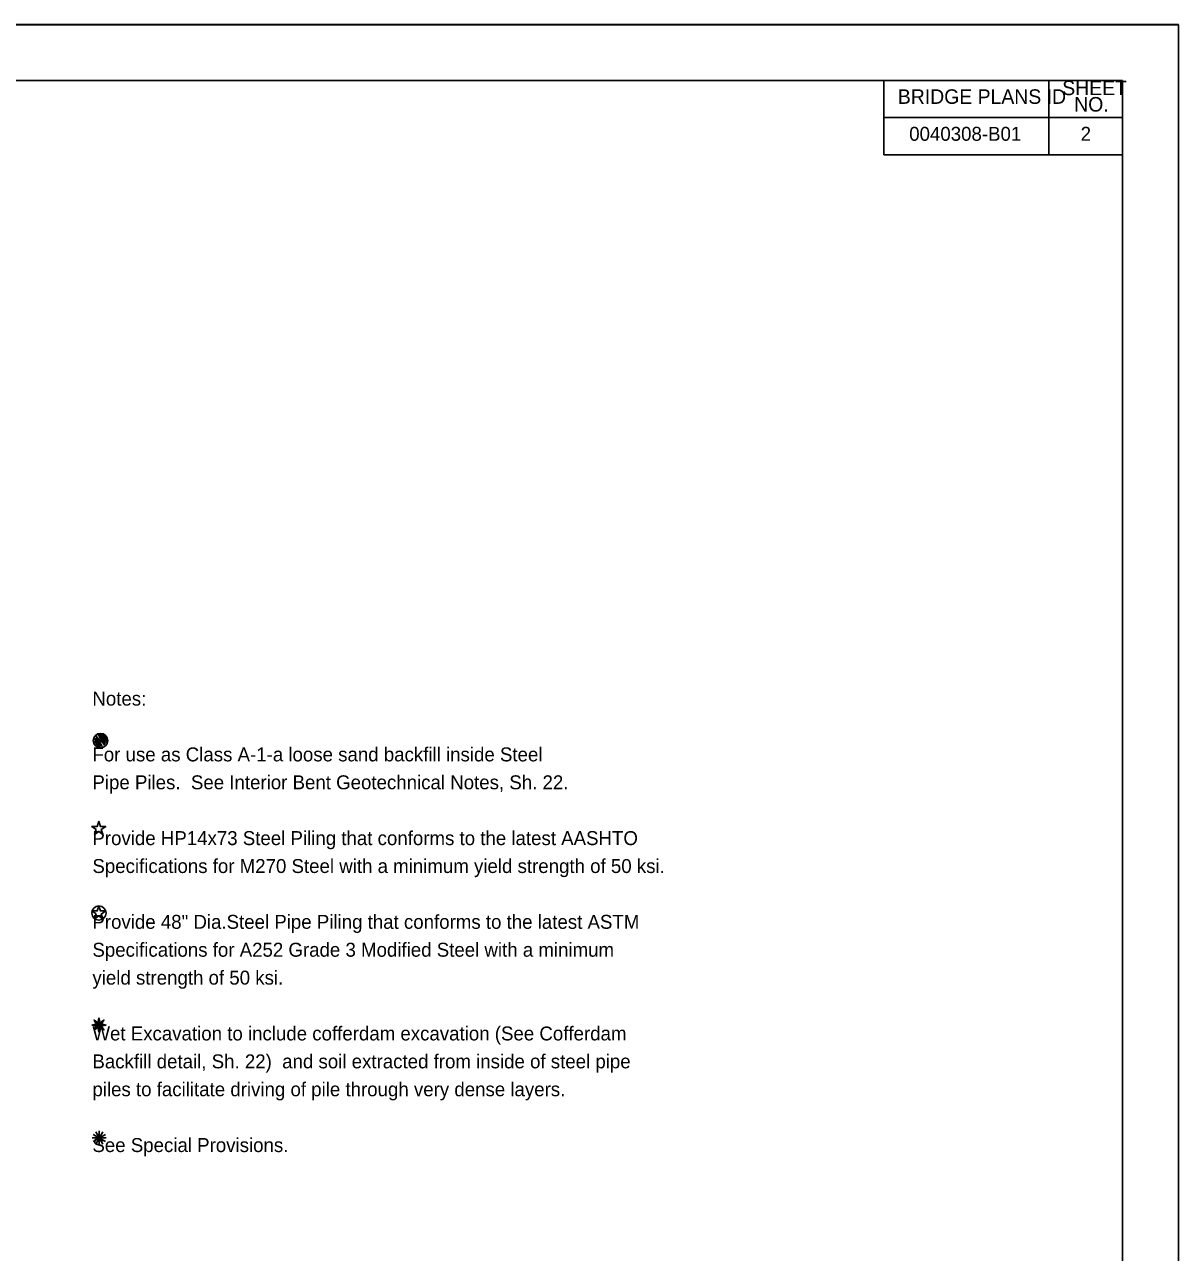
# Model space of a CAD drawing. Extents: x 1334.3 to 1370.4, y 717.9 to 739.9.
# Drawn here: x 1360 to 1370.33, y 728.87 to 739.87 of the extents above; entities that cross this region are included whole.
import ezdxf

# ---------------------------------------------------------------- set-up
doc = ezdxf.new("R2010")
doc.units = 0
for name, color, linetype in [('BR_AUTO DIMENSION', 7, 'Continuous'), ('BR_BORDER LINES', 7, 'Continuous'), ('BR_TEXT', 7, 'Continuous'), ('Default', 7, 'Continuous'), ('RD_SHT_IplotShp', 7, 'Continuous')]:
    doc.layers.add(name, color=color, linetype=linetype)

# ---------------------------------------------------------------- blocks, each defined once
blk = doc.blocks.new('BUBB')
at = {"layer": 'Default'}
for p, q in [((-2.9961, 4.5593), (0, 6.2527)), ((0, 6.2527), (-2.9961, 3.7777)), ((-2.9961, 3.7777), (0.6514, 5.9922)), ((0.6514, 5.9922), (-2.9961, 3.1264)), ((1.433, 5.4711), (-3.2566, 2.0842)), ((-3.2566, 2.0842), (1.954, 5.0803)), ((-2.9961, 3.1264), (1.433, 5.4711)), ((1.954, 5.0803), (-2.475, 1.1724)), ((-2.475, 1.1724), (2.4751, 4.0382)), ((2.4751, 4.0382), (-1.4329, 1.1724)), ((-1.4329, 1.1724), (2.6054, 3.1264)), ((2.6054, 3.1264), (-1.1723, 0.6513)), ((-1.1723, 0.6513), (2.6054, 2.475)), ((2.6054, 2.475), (0.1303, 0.6513))]:
    blk.add_line(p, q, dxfattribs=at)
blk.add_circle((-0.1667, 3.3444), 3.2509, dxfattribs=at)

msp = doc.modelspace()

# ---------------------------------------------------------------- linework, layer by layer
at = {"layer": 'BR_AUTO DIMENSION'}
for points in [[(1360.632, 730.91), (1360.601, 730.903), (1360.632, 730.896)], [(1360.646, 730.93), (1360.619, 730.947), (1360.636, 730.92)], [(1360.632, 730.91), (1360.663, 730.903), (1360.632, 730.896)], [(1360.646, 730.93), (1360.663, 730.903), (1360.636, 730.92)], [(1360.636, 730.886), (1360.663, 730.903), (1360.646, 730.876)], [(1360.67, 730.934), (1360.663, 730.965), (1360.656, 730.934)], [(1360.67, 730.934), (1360.663, 730.903), (1360.656, 730.934)], [(1360.656, 730.872), (1360.663, 730.903), (1360.67, 730.872)], [(1360.69, 730.92), (1360.663, 730.903), (1360.68, 730.93)], [(1360.694, 730.896), (1360.663, 730.903), (1360.694, 730.91)], [(1360.68, 730.876), (1360.663, 730.903), (1360.69, 730.886)], [(1360.69, 730.92), (1360.707, 730.947), (1360.68, 730.93)], [(1360.694, 730.896), (1360.726, 730.903), (1360.694, 730.91)], [(1360.636, 730.886), (1360.619, 730.859), (1360.646, 730.876)], [(1360.656, 730.872), (1360.663, 730.84), (1360.67, 730.872)], [(1360.68, 730.876), (1360.707, 730.859), (1360.69, 730.886)]]:
    msp.add_lwpolyline(points, close=True, dxfattribs=at)
at = {"layer": 'BR_BORDER LINES'}
for p, q in [((1334.334, 739.866), (1370.334, 739.866)), ((1369.834, 739.365), (1336.167, 739.365)), ((1367.694, 738.698), (1367.694, 739.365)), ((1369, 739.365), (1369, 739.365)), ((1369.174, 738.698), (1369.174, 739.365)), ((1369.416, 739.365), (1369.416, 739.365)), ((1369.834, 718.365), (1369.834, 739.365)), ((1367.694, 739.035), (1369.834, 739.035)), ((1369.834, 738.698), (1367.694, 738.698)), ((1369.834, 738.201), (1369.834, 738.698)), ((1369.834, 731.152), (1369.834, 738.201))]:
    msp.add_line(p, q, dxfattribs=at)
at = {"layer": 'BR_TEXT'}
for p, q in [((1360.721, 729.859), (1360.611, 729.923)), ((1360.721, 729.923), (1360.611, 729.859)), ((1360.611, 729.923), (1360.721, 729.859)), ((1360.611, 729.859), (1360.721, 729.923)), ((1360.721, 729.859), (1360.611, 729.923)), ((1360.721, 729.923), (1360.611, 729.859)), ((1360.611, 729.923), (1360.721, 729.859)), ((1360.611, 729.859), (1360.721, 729.923)), ((1360.697, 729.836), (1360.634, 729.946)), ((1360.697, 729.946), (1360.634, 729.836)), ((1360.634, 729.946), (1360.697, 729.836)), ((1360.634, 729.836), (1360.697, 729.946)), ((1360.697, 729.836), (1360.634, 729.946)), ((1360.697, 729.946), (1360.634, 729.836)), ((1360.634, 729.946), (1360.697, 729.836)), ((1360.666, 729.956), (1360.666, 729.828)), ((1360.666, 729.827), (1360.666, 729.955)), ((1360.666, 729.955), (1360.666, 729.827)), ((1360.666, 729.827), (1360.666, 729.955)), ((1360.666, 729.955), (1360.666, 729.827)), ((1360.729, 729.891), (1360.602, 729.891)), ((1360.602, 729.891), (1360.729, 729.891)), ((1360.729, 729.891), (1360.602, 729.891)), ((1360.602, 729.891), (1360.729, 729.891))]:
    msp.add_line(p, q, dxfattribs=at)
for points in [[(1360.638, 732.656), (1360.623, 732.611), (1360.661, 732.638), (1360.698, 732.611), (1360.684, 732.655), (1360.724, 732.683), (1360.676, 732.683), (1360.662, 732.727), (1360.647, 732.683), (1360.599, 732.683)], [(1360.638, 731.898), (1360.623, 731.853), (1360.661, 731.88), (1360.698, 731.852), (1360.684, 731.897), (1360.724, 731.925), (1360.676, 731.925), (1360.662, 731.969), (1360.647, 731.925), (1360.599, 731.925)]]:
    msp.add_lwpolyline(points, close=True, dxfattribs=at)
msp.add_circle((1360.663, 731.906), 0.0636, dxfattribs=at)
at = {"layer": 'RD_SHT_IplotShp'}
msp.add_lwpolyline([(1334.334, 739.865), (1370.334, 739.865), (1370.334, 717.865), (1334.334, 717.865)], close=True, dxfattribs=at)

# ---------------------------------------------------------------- block references
at = {"layer": 'BR_TEXT', "xscale": 0.020000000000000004, "yscale": 0.020000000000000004, "rotation": -90.00000000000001}
msp.add_blockref('BUBB', (1360.61, 733.448), dxfattribs=at)

# ---------------------------------------------------------------- texts
at = {"layer": 'BR_TEXT'}
for s, height, p in [('SHEET', 0.13, (1369.293, 739.234)), ('BRIDGE PLANS ID', 0.13, (1367.82, 739.156)), ('NO.', 0.13, (1369.4, 739.087)), ('0040308-B01', 0.125, (1367.922, 738.825)), ('2', 0.125, (1369.458, 738.825)), ('   Notes:', 0.125, (1360.465, 733.765)), ('   For use as Class A-1-a loose sand backfill inside Steel ', 0.125, (1360.465, 733.265)), ('   Pipe Piles.  See Interior Bent Geotechnical Notes, Sh. 22.', 0.125, (1360.465, 733.015)), ('   Provide HP14x73 Steel Piling that conforms to the latest AASHTO ', 0.125, (1360.465, 732.515)), ('   Specifications for M270 Steel with a minimum yield strength of 50 ksi.', 0.125, (1360.465, 732.265)), ('   Provide 48" Dia.Steel Pipe Piling that conforms to the latest ASTM ', 0.125, (1360.465, 731.765)), ('   Specifications for A252 Grade 3 Modified Steel with a minimum ', 0.125, (1360.465, 731.515)), ('   yield strength of 50 ksi.', 0.125, (1360.465, 731.265)), ('   Wet Excavation to include cofferdam excavation (See Cofferdam ', 0.125, (1360.465, 730.765)), ('   Backfill detail, Sh. 22)  and soil extracted from inside of steel pipe ', 0.125, (1360.465, 730.515)), ('   piles to facilitate driving of pile through very dense layers. ', 0.125, (1360.465, 730.265)), ('   See Special Provisions.', 0.125, (1360.465, 729.765))]:
    msp.add_text(s, height=height, dxfattribs=at).set_placement(p)

doc.saveas('drawing.dxf')
